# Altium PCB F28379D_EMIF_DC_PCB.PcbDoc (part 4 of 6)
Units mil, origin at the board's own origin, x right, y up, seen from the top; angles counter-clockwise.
Board outline 3000 x 1480 mil, 6 copper layers (Top Layer, Signal Layer 1, Signal Layer 2, Signal Layer 3, Signal Layer 4, Bottom Layer), stack 61.4 mil thick; 51 components, 68 nets, 414 pads, 205 vias.
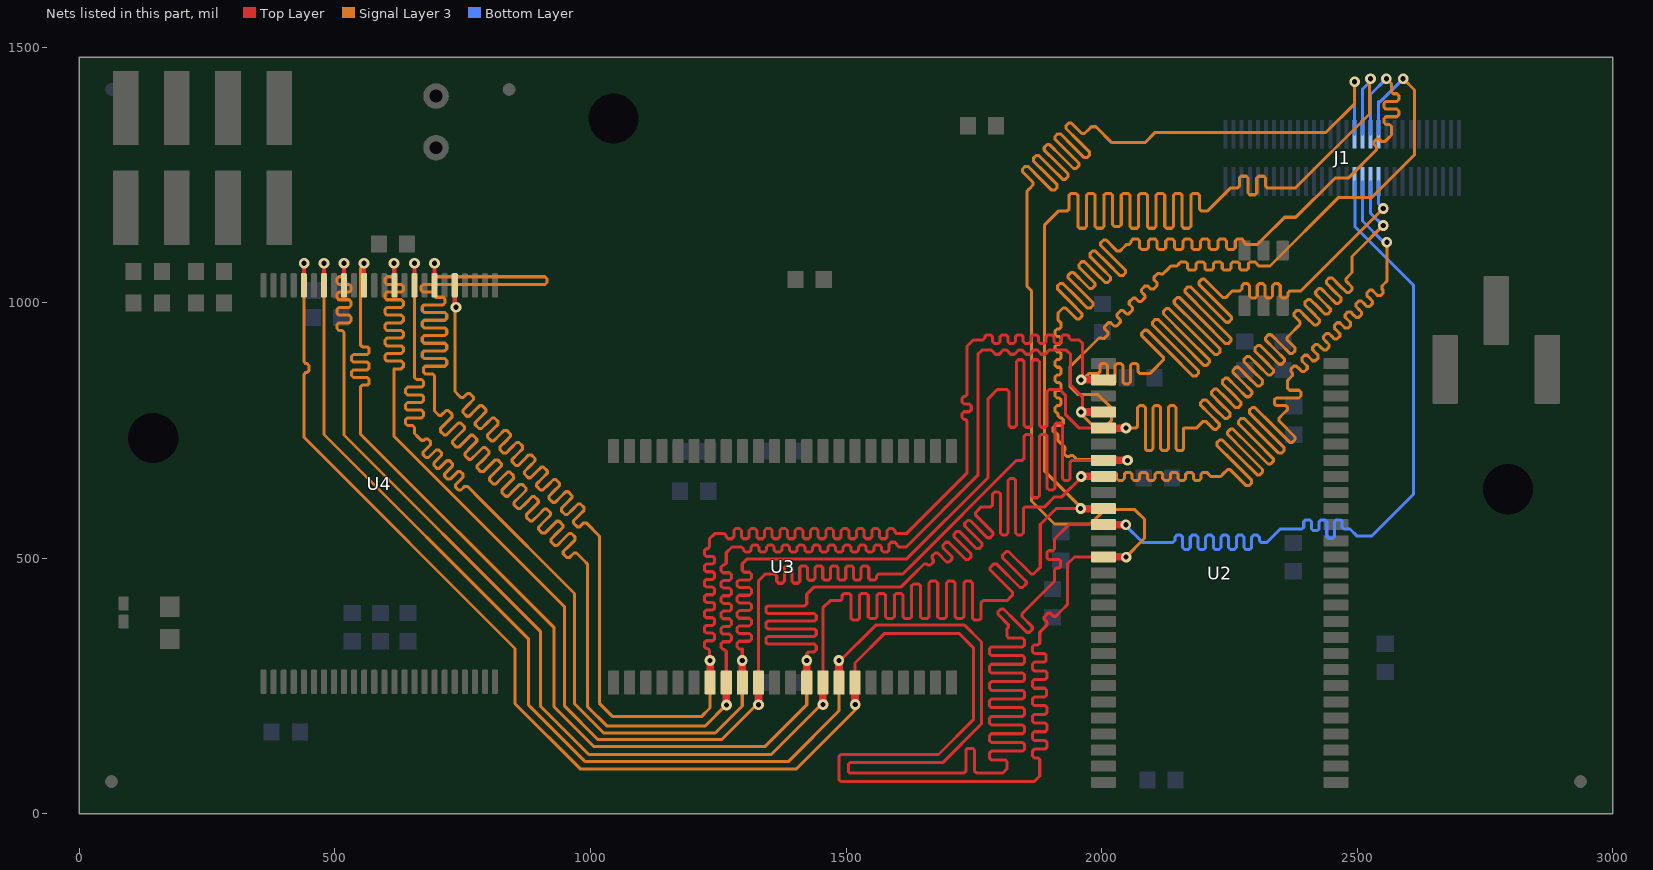
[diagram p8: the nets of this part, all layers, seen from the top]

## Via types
v1: diameter 21, hole 10, Top Layer to Bottom Layer, 204 vias
v2: diameter 20, hole 10, Top Layer to Bottom Layer, 1 vias

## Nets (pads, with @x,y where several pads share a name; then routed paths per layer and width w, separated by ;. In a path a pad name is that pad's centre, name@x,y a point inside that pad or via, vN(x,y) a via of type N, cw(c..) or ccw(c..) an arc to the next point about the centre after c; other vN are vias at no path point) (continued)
EM_D0: J1.21@2541.87,1236.74 U2.2 U3.7 U4.29 | length 6484.8
  Top Layer w6: v1@1234,297 1233,298 1233,316 1233,319.75 1229.25,323.5 1226.75,323.5 1223,327.25 1223,334.75 1226.75,338.5 1233,338.5 1239.25,338.5 1243,342.25 1243,349.75 1239.25,353.5 1233,353.5 1226.75,353.5 1223,357.25 1223,364.75 1226.75,368.5 1233,368.5 1239.25,368.5 1243,372.25 1243,379.75 1239.25,383.5 1233,383.5 1226.75,383.5 1223,387.25 1223,394.75 1226.75,398.5 1233,398.5 1239.25,398.5 1243,402.25 1243,409.75 1239.25,413.5 1233,413.5 1226.75,413.5 1223,417.25 1223,424.75 1226.75,428.5 1233,428.5 1239.25,428.5 1243,432.25 1243,439.75 1239.25,443.5 1233,443.5 1226.75,443.5 1223,447.25 1223,454.75 1226.75,458.5 1233,458.5 1239.25,458.5 1243,462.25 1243,469.75 1239.25,473.5 1233,473.5 1226.75,473.5 1223,477.25 1223,484.75 1226.75,488.5 1233,488.5 1239.25,488.5 1243,492.25 1243,499.75 1239.25,503.5 1233,503.5 1226.75,503.5 1223,507.25 1223,514.75 1226.75,518.5 1229.25,518.5 1233,522.25 1233,532 1233,538 1243,548 1250.5,548 1261.75,548 1265.5,544.25 1265.5,541.75 1269.25,538 1276.75,538 1280.5,541.75 1280.5,548 1280.5,554.25 1284.25,558 1291.75,558 1295.5,554.25 1295.5,548 1295.5,541.75 1299.25,538 1306.75,538 1310.5,541.75 1310.5,548 1310.5,554.25 1314.25,558 1321.75,558 1325.5,554.25 1325.5,548 1325.5,541.75 1329.25,538 1336.75,538 1340.5,541.75 1340.5,548 1340.5,554.25 1344.25,558 1351.75,558 1355.5,554.25 1355.5,548 1355.5,541.75 1359.25,538 1366.75,538 1370.5,541.75 1370.5,548 1370.5,554.25 1374.25,558 1381.75,558 1385.5,554.25 1385.5,548 1385.5,541.75 1389.25,538 1396.75,538 1400.5,541.75 1400.5,548 1400.5,554.25 1404.25,558 1411.75,558 1415.5,554.25 1415.5,548 1415.5,541.75 1419.25,538 1426.75,538 1430.5,541.75 1430.5,548 1430.5,554.25 1434.25,558 1441.75,558 1445.5,554.25 1445.5,548 1445.5,541.75 1449.25,538 1456.75,538 1460.5,541.75 1460.5,548 1460.5,554.25 1464.25,558 1471.75,558 1475.5,554.25 1475.5,548 1475.5,541.75 1479.25,538 1486.75,538 1490.5,541.75 1490.5,548 1490.5,554.25 1494.25,558 1501.75,558 1505.5,554.25 1505.5,548 1505.5,541.75 1509.25,538 1516.75,538 1520.5,541.75 1520.5,548 1520.5,554.25 1524.25,558 1531.75,558 1535.5,554.25 1535.5,548 1535.5,541.75 1539.25,538 1546.75,538 1550.5,541.75 1550.5,548 1550.5,554.25 1554.25,558 1561.75,558 1565.5,554.25 1565.5,548 1565.5,541.75 1569.25,538 1576.75,538 1580.5,541.75 1580.5,548 1580.5,554.25 1584.25,558 1591.75,558 1595.5,554.25 1595.5,551.75 1599.25,548 1610.5,548 1611,548 1618,548 1737,667 1737,764 1737,767.75 1733.25,771.5 1730.75,771.5 1727,775.25 1727,782.75 1730.75,786.5 1737,786.5 1741.25,786.5 1745,790.25 1745,797.75 1741.25,801.5 1737,801.5 1730.75,801.5 1727,805.25 1727,812.75 1730.75,816.5 1733.25,816.5 1737,820.25 1737,899 1737,915 1749,927 1764,927 1767.75,927 1771.5,930.75 1771.5,933.25 1775.25,937 1782.75,937 1786.5,933.25 1786.5,927 1786.5,923.75 1790.25,920 1797.75,920 1801.5,923.75 1801.5,927 1801.5,933.25 1805.25,937 1812.75,937 1816.5,933.25 1816.5,927 1816.5,923.75 1820.25,920 1827.75,920 1831.5,923.75 1831.5,927 1831.5,933.25 1835.25,937 1842.75,937 1846.5,933.25 1846.5,927 1846.5,923.75 1850.25,920 1857.75,920 1861.5,923.75 1861.5,927 1861.5,933.25 1865.25,937 1872.75,937 1876.5,933.25 1876.5,927 1876.5,923.75 1880.25,920 1887.75,920 1891.5,923.75 1891.5,927 1891.5,933.25 1895.25,937 1902.75,937 1906.5,933.25 1906.5,927 1906.5,923.75 1910.25,920 1917.75,920 1921.5,923.75 1921.5,927 1921.5,933.25 1925.25,937 1932.75,937 1936.5,933.25 1936.5,930.75 1940.25,927 1951.5,927 1956,927 1963.05,919.95 v1@1963.05,848.95
  Top Layer w8: U4.29@734.64,1033.8 734.64,996.36 v1@737,994
  Top Layer w15: U3.7@1234.27,256.62 v1@1234.27,290.73 ; v1@1963.05,848.95 U2.2@2003.64,848.95
  Signal Layer 3 w6: v1(737,991) v1@735,989 ; v1@737,994 735,992 v1@735,989 ; v1@1234,297 1234,207 1217,190 1044,190 1017.5,216.5 1017.5,540 1017.5,543.5 991.83,569.17 987.02,569.17 979.1,561.25 974.29,561.25 967.08,568.46 967.08,573.27 977.41,583.59 987.73,593.92 987.73,598.73 980.52,605.94 975.71,605.94 965.39,595.61 955.06,585.29 950.25,585.29 943.04,592.5 943.04,597.31 953.36,607.64 963.69,617.96 963.69,622.77 956.48,629.98 951.67,629.98 941.34,619.66 931.02,609.33 926.21,609.33 919,616.55 919,621.35 929.32,631.68 939.65,642 939.65,646.81 932.43,654.02 927.63,654.02 917.3,643.7 906.98,633.37 902.17,633.37 894.96,640.59 894.96,645.4 905.28,655.72 915.6,666.04 915.6,670.85 908.39,678.06 903.58,678.06 893.26,667.74 882.94,657.42 878.13,657.42 870.92,664.63 870.92,669.44 881.24,679.76 891.56,690.08 891.56,694.89 884.35,702.11 879.54,702.11 869.22,691.78 858.89,681.46 854.09,681.46 846.87,688.67 846.87,693.48 857.2,703.8 867.52,714.13 867.52,718.93 860.31,726.15 855.5,726.15 845.18,715.82 834.85,705.5 830.04,705.5 822.83,712.71 822.83,717.52 833.16,727.84 843.48,738.17 843.48,742.98 836.27,750.19 831.46,750.19 821.14,739.86 810.81,729.54 806,729.54 798.79,736.75 798.79,741.56 809.11,751.89 819.44,762.21 819.44,767.02 812.23,774.23 807.42,774.23 797.09,763.91 786.77,753.58 781.96,753.58 774.75,760.8 774.75,765.6 785.07,775.93 795.4,786.25 795.4,791.06 788.18,798.27 783.38,798.27 773.05,787.95 762.73,777.62 757.92,777.62 750.71,784.84 750.71,789.64 761.03,799.97 771.36,810.29 771.36,815.1 764.14,822.31 759.33,822.31 751.41,814.39 746.61,814.39 743,818 735,826 v1@735,989 ; v1@1963.05,848.95 1975.1,861 1982,861 1992.75,861 1996.5,864.75 1996.5,877.25 2000.25,881 2007.75,881 2011.5,877.25 2011.5,861 2011.5,844.75 2015.25,841 2022.75,841 2026.5,844.75 2026.5,861 2026.5,877.25 2030.25,881 2037.75,881 2041.5,877.25 2041.5,861 2041.5,844.75 2045.25,841 2052.75,841 2056.5,844.75 2056.5,861 2056.5,877.25 2060.25,881 2067.75,881 2071.5,877.25 2071.5,864.75 2075.25,861 2086.5,861 2094,861 2099,866 2120.77,887.77 2120.77,893.07 2078.52,935.32 2078.52,940.62 2083.82,945.93 2089.12,945.93 2134.02,901.02 2178.93,856.12 2184.23,856.12 2189.53,861.43 2189.53,866.73 2144.63,911.63 2099.73,956.53 2099.73,961.84 2105.03,967.14 2110.34,967.14 2155.24,922.24 2200.14,877.34 2205.44,877.34 2210.75,882.64 2210.75,887.94 2165.84,932.84 2120.94,977.75 2120.94,983.05 2126.25,988.35 2131.55,988.35 2176.45,943.45 2221.35,898.55 2226.66,898.55 2231.96,903.85 2231.96,909.16 2187.06,954.06 2142.16,998.96 2142.16,1004.26 2147.46,1009.57 2152.76,1009.57 2197.66,964.66 2242.57,919.76 2247.87,919.76 2253.17,925.07 2253.17,930.37 2208.27,975.27 2163.37,1020.17 2163.37,1025.48 2168.67,1030.78 2173.97,1030.78 2218.88,985.88 2243.22,961.53 2248.52,961.53 2253.83,966.84 2253.83,972.14 2229.48,996.48 2190.76,1035.21 2190.76,1040.51 2196.06,1045.82 2201.36,1045.82 2237.44,1009.74 2242.74,1009.74 2250.7,1017.7 2256,1023 2267,1023 2270.75,1023 2274.5,1026.75 2274.5,1033.25 2278.25,1037 2285.75,1037 2289.5,1033.25 2289.5,1023 2289.5,1012.75 2293.25,1009 2300.75,1009 2304.5,1012.75 2304.5,1023 2304.5,1033.25 2308.25,1037 2315.75,1037 2319.5,1033.25 2319.5,1023 2319.5,1012.75 2323.25,1009 2330.75,1009 2334.5,1012.75 2334.5,1023 2334.5,1033.25 2338.25,1037 2345.75,1037 2349.5,1033.25 2349.5,1023 2349.5,1012.75 2353.25,1009 2360.75,1009 2364.5,1012.75 2364.5,1019.25 2368.25,1023 2379.5,1023 2380,1023 2390,1023 v1(2551,1184)
  Bottom Layer w6: J1.21@2541.87,1236.74 2541.87,1193.13 v1(2551,1184)
  other v1: 1234,300 1960.05,848.95
EM_D1: J1.22@2541.87,1329.26 U2.4 U3.8 U4.31 | length 6431.8
  Top Layer w6: U3.8@1265.76,256.62 1265.76,314 1265.76,317.75 1262.01,321.5 1259.51,321.5 1255.76,325.25 1255.76,332.75 1259.51,336.5 1265.76,336.5 1272.01,336.5 1275.76,340.25 1275.76,347.75 1272.01,351.5 1265.76,351.5 1259.51,351.5 1255.76,355.25 1255.76,362.75 1259.51,366.5 1265.76,366.5 1272.01,366.5 1275.76,370.25 1275.76,377.75 1272.01,381.5 1265.76,381.5 1259.51,381.5 1255.76,385.25 1255.76,392.75 1259.51,396.5 1265.76,396.5 1272.01,396.5 1275.76,400.25 1275.76,407.75 1272.01,411.5 1265.76,411.5 1259.51,411.5 1255.76,415.25 1255.76,422.75 1259.51,426.5 1265.76,426.5 1272.01,426.5 1275.76,430.25 1275.76,437.75 1272.01,441.5 1265.76,441.5 1259.51,441.5 1255.76,445.25 1255.76,452.75 1259.51,456.5 1265.76,456.5 1272.01,456.5 1275.76,460.25 1275.76,467.75 1272.01,471.5 1265.76,471.5 1259.51,471.5 1255.76,475.25 1255.76,482.75 1259.51,486.5 1262.01,486.5 1265.76,490.25 1265.76,497 1265.76,510.76 1277,522 1284.5,522 1295.75,522 1299.5,518.25 1299.5,515.75 1303.25,512 1310.75,512 1314.5,515.75 1314.5,522 1317.89,525.39 1326.11,525.39 1329.5,522 1329.5,515.75 1333.25,512 1340.75,512 1344.5,515.75 1344.5,522 1347.89,525.39 1356.11,525.39 1359.5,522 1359.5,515.75 1363.25,512 1370.75,512 1374.5,515.75 1374.5,522 1377.89,525.39 1386.11,525.39 1389.5,522 1389.5,515.75 1393.25,512 1400.75,512 1404.5,515.75 1404.5,522 1407.89,525.39 1416.11,525.39 1419.5,522 1419.5,515.75 1423.25,512 1430.75,512 1434.5,515.75 1434.5,522 1437.89,525.39 1446.11,525.39 1449.5,522 1449.5,515.75 1453.25,512 1460.75,512 1464.5,515.75 1464.5,522 1467.89,525.39 1476.11,525.39 1479.5,522 1479.5,515.75 1483.25,512 1490.75,512 1494.5,515.75 1494.5,522 1497.89,525.39 1506.11,525.39 1509.5,522 1509.5,515.75 1513.25,512 1520.75,512 1524.5,515.75 1524.5,522 1527.89,525.39 1536.11,525.39 1539.5,522 1539.5,515.75 1543.25,512 1550.75,512 1554.5,515.75 1554.5,522 1557.89,525.39 1566.11,525.39 1569.5,522 1569.5,515.75 1573.25,512 1580.75,512 1584.5,515.75 1584.5,522 1584.5,527.37 1588.25,531.12 1595.75,531.12 1599.5,527.37 1599.5,525.75 1603.25,522 1605,522 1618,522 1758,662 1758,899 1766,907 1773.5,907 1784.75,907 1788.5,903.25 1788.5,902.75 1792.25,899 1799.75,899 1803.5,902.75 1803.5,903.25 1807.25,907 1814.75,907 1818.5,903.25 1818.5,902.75 1822.25,899 1829.75,899 1833.5,902.75 1833.5,903.25 1837.25,907 1844.75,907 1848.5,903.25 1848.5,902.75 1852.25,899 1859.75,899 1863.5,902.75 1863.5,903.25 1867.25,907 1874.75,907 1878.5,903.25 1878.5,902.75 1882.25,899 1889.75,899 1893.5,902.75 1893.5,903.25 1897.25,907 1908.5,907 1923.5,907 1926,907 1931,907 1939,899 1939,839 1963.04,814.96 v1@1963.04,785.96
  Top Layer w8: v1@695,1076 695.27,1075.73 U4.31@695.27,1033.8
  Top Layer w15: U3.8@1265.76,256.62 1265.76,222.24 v1@1266,222 ; v1@1963.04,785.96 U2.4@2003.64,785.96
  Signal Layer 3 w6: v1@695,1073 695,1065.5 695,1054.25 698.75,1050.5 911.25,1050.5 915,1046.75 915,1039.25 911.25,1035.5 695,1035.5 672.75,1035.5 669,1031.75 669,1024.25 672.75,1020.5 691.25,1020.5 695,1016.75 695,1013 697.5,1010.5 711.95,1010.5 715.7,1006.75 715.7,999.25 711.95,995.5 695,995.5 674.75,995.5 671,991.75 671,984.25 674.75,980.5 695,980.5 715.25,980.5 719,976.75 719,969.25 715.25,965.5 695,965.5 674.75,965.5 671,961.75 671,954.25 674.75,950.5 695,950.5 715.25,950.5 719,946.75 719,939.25 715.25,935.5 695,935.5 674.75,935.5 671,931.75 671,924.25 674.75,920.5 695,920.5 715.25,920.5 719,916.75 719,909.25 715.25,905.5 695,905.5 674.75,905.5 671,901.75 671,894.25 674.75,890.5 695,890.5 715.25,890.5 719,886.75 719,879.25 715.25,875.5 695,875.5 676.82,875.5 673.07,871.75 673.07,864.25 676.82,860.5 691.25,860.5 695,856.75 695,853 695,788 700,783 703.61,779.39 708.41,779.39 717.61,788.59 722.41,788.59 729.63,781.37 729.63,776.56 718.03,764.97 706.44,753.37 706.44,748.56 713.65,741.35 718.46,741.35 730.05,752.95 741.65,764.54 746.46,764.54 753.67,757.33 753.67,752.52 742.07,740.93 730.48,729.33 730.48,724.52 737.69,717.31 742.5,717.31 754.09,728.91 765.69,740.5 770.5,740.5 777.71,733.29 777.71,728.48 766.11,716.89 754.52,705.29 754.52,700.48 761.73,693.27 766.54,693.27 778.14,704.86 789.73,716.46 794.54,716.46 801.75,709.25 801.75,704.44 790.16,692.84 778.56,681.25 778.56,676.44 785.77,669.23 790.58,669.23 802.18,680.82 813.77,692.42 818.58,692.42 825.79,685.21 825.79,680.4 814.2,668.8 802.6,657.21 802.6,652.4 809.81,645.19 814.62,645.19 826.22,656.78 837.81,668.38 842.62,668.38 849.84,661.16 849.84,656.36 838.24,644.76 826.64,633.16 826.64,628.36 833.86,621.14 838.66,621.14 850.26,632.74 861.86,644.34 866.66,644.34 873.88,637.12 873.88,632.31 862.28,620.72 850.69,609.12 850.69,604.31 857.9,597.1 862.71,597.1 874.3,608.7 885.9,620.29 890.71,620.29 897.92,613.08 897.92,608.27 886.32,596.68 874.73,585.08 874.73,580.27 881.94,573.06 886.75,573.06 898.34,584.66 909.94,596.25 914.75,596.25 921.96,589.04 921.96,584.23 910.36,572.64 898.77,561.04 898.77,556.23 905.98,549.02 910.79,549.02 922.39,560.61 933.98,572.21 938.79,572.21 946,565 946,560.19 934.41,548.59 922.81,537 922.81,532.19 930.02,524.98 934.83,524.98 946.43,536.57 958.02,548.17 962.83,548.17 970.04,540.96 970.04,536.15 958.45,524.55 946.85,512.96 946.85,508.15 954.06,500.94 958.87,500.94 968.06,510.13 972.87,510.13 987.5,495.5 994,489 994,210 1032,172 1225,172 v1(1266,213) ; v1@1264,215 v1@1266,217 ; v1@1963.04,785.96 1963.04,778.96 1986,756 2006,756 2019,769 2019,794 1993,820 1954,820 1938,836 1938,874 1994.86,930.86 1999.66,930.86 2000.51,930.01 2005.32,930.01 2012.53,937.22 2012.53,942.03 2009.28,945.28 2006.03,948.53 2006.03,953.34 2013.24,960.55 2018.05,960.55 2021.3,957.3 2024.55,954.05 2029.36,954.05 2036.58,961.26 2036.58,966.07 2033.32,969.32 2030.07,972.58 2030.07,977.38 2037.28,984.6 2042.09,984.6 2045.34,981.34 2048.6,978.09 2053.4,978.09 2060.62,985.3 2060.62,990.11 2057.36,993.36 2054.11,996.62 2054.11,1001.43 2061.32,1008.64 2066.13,1008.64 2069.39,1005.39 2072.64,1002.13 2077.45,1002.13 2084.66,1009.35 2084.66,1014.15 2081.41,1017.41 2078.15,1020.66 2078.15,1025.47 2085.37,1032.68 2090.17,1032.68 2093.43,1029.43 2096.68,1026.17 2101.49,1026.17 2108.7,1033.39 2108.7,1038.2 2105.45,1041.45 2102.2,1044.7 2102.2,1049.51 2109.41,1056.72 2114.22,1056.72 2115.06,1055.87 2119.87,1055.87 2129.49,1065.49 2135.5,1071.5 2147.6,1071.5 2151,1074.9 2151,1076.1 2154.4,1079.5 2164.6,1079.5 2168,1076.1 2168,1071.5 2168,1066.9 2171.4,1063.5 2181.6,1063.5 2185,1066.9 2185,1071.5 2185,1076.1 2188.4,1079.5 2198.6,1079.5 2202,1076.1 2202,1071.5 2202,1066.9 2205.4,1063.5 2215.6,1063.5 2219,1066.9 2219,1071.5 2219,1076.1 2222.4,1079.5 2232.6,1079.5 2236,1076.1 2236,1071.5 2236,1066.9 2239.4,1063.5 2249.6,1063.5 2253,1066.9 2253,1071.5 2253,1076.1 2256.4,1079.5 2266.6,1079.5 2270,1076.1 2270,1071.5 2270,1066.9 2273.4,1063.5 2283.6,1063.5 2287,1066.9 2287,1071.5 2287,1076.1 2290.4,1079.5 2300.6,1079.5 2304,1076.1 2304,1074.9 2307.4,1071.5 2321,1071.5 2329.5,1071.5 2464,1206 2529,1206 2612,1289 2612,1416 v1(2590,1438) ; v1@2587,1438 v1@2588.5,1436.5
  Bottom Layer w6: J1.22@2541.87,1329.26 2541.87,1392.87 2544.87,1392.87 v1(2590,1438)
  other v1: 1960.04,785.96 695,1077
EM_D2: J1.23@2526.12,1236.74 U2.5 U3.9 U4.33 | length 6444.2
  Top Layer w6: v1@1297,297 v1(1297,300) 1297,322 1296.5,322.5 1290.77,322.5 1287.02,326.25 1287.02,333.75 1290.77,337.5 1297,337.5 1311.25,337.5 1315,341.25 1315,348.75 1311.25,352.5 1297,352.5 1290.77,352.5 1287.02,356.25 1287.02,363.75 1290.77,367.5 1297,367.5 1311.25,367.5 1315,371.25 1315,378.75 1311.25,382.5 1297,382.5 1290.77,382.5 1287.02,386.25 1287.02,393.75 1290.77,397.5 1297,397.5 1311.25,397.5 1315,401.25 1315,408.75 1311.25,412.5 1297,412.5 1290.77,412.5 1287.02,416.25 1287.02,423.75 1290.77,427.5 1297,427.5 1311.25,427.5 1315,431.25 1315,438.75 1311.25,442.5 1297,442.5 1290.77,442.5 1287.02,446.25 1287.02,453.75 1290.77,457.5 1297,457.5 1311.25,457.5 1315,461.25 1315,468.75 1311.25,472.5 1300.75,472.5 1297,476.25 1297,480 1297,489 1306,498 1618,498 1778,658 1778,812 1796,830 1803.5,830 1814.75,830 1818.5,826.25 1818.5,759.88 1822.25,756.13 1829.75,756.13 1833.5,759.88 1833.5,830 1833.5,884.5 1837.25,888.25 1844.75,888.25 1848.5,884.5 1848.5,830 1848.5,759.88 1852.25,756.13 1859.75,756.13 1863.5,759.88 1863.5,830 1863.5,884.5 1867.25,888.25 1874.75,888.25 1878.5,884.5 1878.5,830 1878.5,759.88 1882.25,756.13 1889.75,756.13 1893.5,759.88 1893.5,826.25 1897.25,830 1918,830 1929,819 1929,781.46 1956,754.46 U2.5@2003.64,754.46
  Top Layer w8: U4.33@655.9,1033.8 655.9,1075.9 v1@656,1076
  Top Layer w15: U3.9@1297.26,256.62 v1@1297.26,290.74 ; U2.5@2003.64,754.46 v1(2047.54,754.46)
  Signal Layer 3 w6: v1@656,1073 656,857 656,853.25 659.75,849.5 669.89,849.5 673.64,845.75 673.64,838.25 669.89,834.5 656,834.5 642.11,834.5 638.36,830.75 638.36,823.25 642.11,819.5 656,819.5 669.89,819.5 673.64,815.75 673.64,808.25 669.89,804.5 656,804.5 642.11,804.5 638.36,800.75 638.36,793.25 642.11,789.5 656,789.5 669.89,789.5 673.64,785.75 673.64,778.25 669.89,774.5 656,774.5 642.11,774.5 638.36,770.75 638.36,763.25 642.11,759.5 652.25,759.5 656,755.75 656,744.5 656,744 661.3,738.7 669.26,730.74 674.56,730.74 676.81,732.99 682.12,732.99 687.42,727.69 687.42,722.39 682.52,717.48 672.69,707.66 672.69,702.36 678,697.05 683.3,697.05 693.12,706.88 698.03,711.78 703.33,711.78 708.63,706.48 708.63,701.18 703.73,696.27 693.91,686.45 693.91,681.14 699.21,675.84 704.51,675.84 714.34,685.66 719.24,690.57 724.54,690.57 729.85,685.27 729.85,679.96 724.94,675.06 715.12,665.23 715.12,659.93 720.42,654.63 725.73,654.63 735.55,664.45 740.45,669.36 745.76,669.36 751.06,664.05 751.06,658.75 746.16,653.84 736.33,644.02 736.33,638.72 741.63,633.41 746.94,633.41 754.11,640.59 759.41,640.59 787.5,612.5 969,431 969,215 1026,158 1244,158 1297,211 v1@1297,297 ; v1(2047.54,754.46) 2063,754.46 2066.75,754.46 2070.5,758.21 2070.5,794.71 2074.25,798.46 2081.75,798.46 2085.5,794.71 2085.5,754.46 2085.5,714.21 2089.25,710.46 2096.75,710.46 2100.5,714.21 2100.5,754.46 2100.5,794.71 2104.25,798.46 2111.75,798.46 2115.5,794.71 2115.5,754.46 2115.5,714.21 2119.25,710.46 2126.75,710.46 2130.5,714.21 2130.5,754.46 2130.5,794.71 2134.25,798.46 2141.75,798.46 2145.5,794.71 2145.5,754.46 2145.5,714.21 2149.25,710.46 2156.75,710.46 2160.5,714.21 2160.5,753.96 2161,754.46 2185.46,754.46 2190.77,759.77 2198.72,767.72 2204.03,767.72 2219.61,752.14 2224.91,752.14 2230.22,757.44 2230.22,762.74 2211.98,780.98 2193.74,799.22 2193.74,804.52 2199.05,809.82 2204.35,809.82 2222.59,791.59 2240.82,773.35 2246.13,773.35 2251.43,778.65 2251.43,783.96 2233.19,802.19 2214.96,820.43 2214.96,825.73 2220.26,831.04 2225.56,831.04 2243.8,812.8 2262.04,794.56 2267.34,794.56 2272.64,799.87 2272.64,805.17 2254.41,823.41 2236.17,841.64 2236.17,846.95 2241.47,852.25 2246.78,852.25 2265.01,834.01 2283.25,815.78 2288.55,815.78 2293.86,821.08 2293.86,826.38 2275.62,844.62 2257.38,862.86 2257.38,868.16 2262.69,873.46 2267.99,873.46 2286.23,855.23 2304.46,836.99 2309.77,836.99 2315.07,842.29 2315.07,847.6 2296.83,865.83 2278.6,884.07 2278.6,889.37 2283.9,894.68 2289.2,894.68 2307.44,876.44 2325.68,858.2 2330.98,858.2 2336.28,863.51 2336.28,868.81 2318.05,887.05 2299.81,905.28 2299.81,910.59 2305.11,915.89 2310.42,915.89 2328.65,897.65 2346.89,879.42 2352.19,879.42 2357.5,884.72 2357.5,890.02 2339.26,908.26 2321.02,926.5 2321.02,931.8 2326.33,937.1 2331.63,937.1 2349.87,918.87 2368.1,900.63 2373.41,900.63 2378.71,905.93 2378.71,911.24 2363.12,926.82 2363.12,932.12 2367.5,936.5 2385.5,954.5 2388.15,957.15 2388.15,962.45 2376.48,974.12 2376.48,979.43 2381.79,984.73 2387.09,984.73 2401.41,970.41 2415.73,956.09 2421.03,956.09 2426.34,961.39 2426.34,966.7 2412.02,981.02 2397.7,995.34 2397.7,1000.64 2403,1005.94 2408.3,1005.94 2422.62,991.62 2436.94,977.3 2442.25,977.3 2447.55,982.61 2447.55,987.91 2433.23,1002.23 2418.91,1016.55 2418.91,1021.85 2424.21,1027.16 2429.52,1027.16 2443.84,1012.84 2458.16,998.52 2463.46,998.52 2468.76,1003.82 2468.76,1009.12 2454.44,1023.44 2440.12,1037.76 2440.12,1043.07 2445.43,1048.37 2450.73,1048.37 2465.05,1034.05 2479.37,1019.73 2484.67,1019.73 2489.97,1025.03 2489.97,1030.34 2478.31,1042 2478.31,1047.31 2485,1054 2490,1059 2490,1090 v1(2551,1151)
  Bottom Layer w6: J1.23@2526.12,1236.74 2526.12,1174.88 2550,1151 v1(2551,1151)
  other v1: 656,1077
EM_D3: J1.24@2526.12,1329.26 U2.7 U3.10 U4.35 | length 6434
  Top Layer w6: U3.10@1328.76,256.62 1328.76,455.76 1342,469 1349.5,469 1360.75,469 1364.5,465.25 1364.5,454.75 1368.25,451 1375.75,451 1379.5,454.75 1379.5,469 1379.5,481.25 1383.25,485 1390.75,485 1394.5,481.25 1394.5,469 1394.5,454.75 1398.25,451 1405.75,451 1409.5,454.75 1409.5,469 1409.5,481.25 1413.25,485 1420.75,485 1424.5,481.25 1424.5,469 1424.5,460.55 1428.25,456.8 1435.75,456.8 1439.5,460.55 1439.5,469 1439.5,481.25 1443.25,485 1450.75,485 1454.5,481.25 1454.5,469 1454.5,460.75 1458.25,457 1465.75,457 1469.5,460.75 1469.5,469 1469.5,481.25 1473.25,485 1480.75,485 1484.5,481.25 1484.5,469 1484.5,460.75 1488.25,457 1495.75,457 1499.5,460.75 1499.5,469 1499.5,481.25 1503.25,485 1510.75,485 1514.5,481.25 1514.5,469 1514.5,460.75 1518.25,457 1525.75,457 1529.5,460.75 1529.5,469 1529.5,481.25 1533.25,485 1540.75,485 1544.5,481.25 1544.5,469 1544.5,460.75 1548.25,457 1555.75,457 1559.5,460.75 1559.5,465.25 1563.25,469 1611,469 1616.3,474.3 1626.5,484.5 1833.47,691.47 1841,691.47 1844.75,691.47 1848.5,695.22 1848.5,738.62 1852.25,742.37 1859.75,742.37 1863.5,738.62 1863.5,691.47 1863.5,621.98 1867.25,618.23 1874.75,618.23 1878.5,621.98 1878.5,691.47 1878.5,738.62 1882.25,742.37 1889.75,742.37 1893.5,738.62 1893.5,691.47 1893.5,637.1 1897.25,633.35 1904.75,633.35 1908.5,637.1 1908.5,691.47 1908.5,760.96 1912.25,764.71 1919.75,764.71 1923.5,760.96 1923.5,691.47 1923.5,655.6 1927.25,651.85 1934.75,651.85 1938.5,655.6 1938.5,687.72 1942.25,691.47 1947,691.47 U2.7@2003.64,691.47
  Top Layer w8: v1@616,1076 616.53,1075.47 U4.35@616.53,1033.8
  Top Layer w15: v1@1328.76,222.24 U3.10@1328.76,256.62 ; U2.7@2003.64,691.47 v1(2050.53,691.47)
  Signal Layer 3 w6: v1@616,1073 616,1065.5 616,1054.25 612.25,1050.5 601.79,1050.5 598.04,1046.75 598.04,1039.25 601.79,1035.5 616,1035.5 630.21,1035.5 633.96,1031.75 633.96,1024.25 630.21,1020.5 616,1020.5 601.79,1020.5 598.04,1016.75 598.04,1009.25 601.79,1005.5 616,1005.5 630.21,1005.5 633.96,1001.75 633.96,994.25 630.21,990.5 616,990.5 601.79,990.5 598.04,986.75 598.04,979.25 601.79,975.5 616,975.5 630.21,975.5 633.96,971.75 633.96,964.25 630.21,960.5 616,960.5 601.79,960.5 598.04,956.75 598.04,949.25 601.79,945.5 616,945.5 630.21,945.5 633.96,941.75 633.96,934.25 630.21,930.5 616,930.5 601.79,930.5 598.04,926.75 598.04,919.25 601.79,915.5 616,915.5 630.21,915.5 633.96,911.75 633.96,904.25 630.21,900.5 616,900.5 601.79,900.5 598.04,896.75 598.04,889.25 601.79,885.5 616,885.5 630.21,885.5 633.96,881.75 633.96,874.25 630.21,870.5 616.5,870.5 616,870 616,738 949.5,404.5 949.5,210.5 1015,145 1256.51,145 v1@1328.76,217.24 ; v1(2050.53,691.47) 2049,693 2038,693 2030.75,693 2028.5,695.25 2024.75,699 2017.25,699 2013.5,695.25 2013.5,693 2013.5,690.75 2009.75,687 2002.25,687 1998.5,690.75 1998.5,693 1998.5,695.25 1994.75,699 1987.25,699 1983.5,695.25 1981.25,693 1976,693 1952,693 1948.5,696.5 1944.17,700.83 1938.86,700.83 1937.1,699.06 1931.79,699.06 1926.49,704.37 1926.49,709.67 1928.26,711.44 1928.26,716.74 1920.3,724.7 1915,730 1915,740.75 1911.25,744.5 1908.75,744.5 1905,748.25 1905,755.75 1908.75,759.5 1915,759.5 1921.25,759.5 1925,763.25 1925,770.75 1921.25,774.5 1918.75,774.5 1915,778.25 1915,782 1913.5,783.5 1912.75,783.5 1909,787.25 1909,794.75 1912.75,798.5 1915,798.5 1917.25,798.5 1921,802.25 1921,809.75 1917.25,813.5 1915,813.5 1912.75,813.5 1909,817.25 1909,824.75 1912.75,828.5 1915,828.5 1917.25,828.5 1921,832.25 1921,839.75 1917.25,843.5 1915,843.5 1912.75,843.5 1909,847.25 1909,854.75 1912.75,858.5 1915,858.5 1917.25,858.5 1921,862.25 1921,869.75 1917.25,873.5 1915,873.5 1912.75,873.5 1909,877.25 1909,884.75 1912.75,888.5 1915,888.5 1917.25,888.5 1921,892.25 1921,899.75 1917.25,903.5 1915,903.5 1912.75,903.5 1909,907.25 1909,914.75 1912.75,918.5 1915,918.5 1917.25,918.5 1921,922.25 1921,929.75 1917.25,933.5 1915,933.5 1912.75,933.5 1909,937.25 1909,944.75 1912.75,948.5 1915,948.5 1917.25,948.5 1921,952.25 1921,959.75 1917.25,963.5 1915,965.75 1915,971 1915,980 1917.5,982.5 1924.37,989.37 1929.68,989.37 1951.24,967.81 1956.55,967.81 1961.85,973.11 1961.85,978.41 1937.63,1002.63 1913.41,1026.85 1913.41,1032.15 1918.72,1037.46 1924.02,1037.46 1948.24,1013.24 1972.46,989.02 1977.76,989.02 1983.06,994.32 1983.06,999.63 1958.84,1023.84 1934.63,1048.06 1934.63,1053.37 1939.93,1058.67 1945.23,1058.67 1969.45,1034.45 1976.2,1027.7 1981.5,1027.7 1986.81,1033 1986.81,1038.31 1980.06,1045.06 1955.84,1069.28 1955.84,1074.58 1961.14,1079.88 1966.45,1079.88 1990.66,1055.66 2006.95,1039.38 2012.26,1039.38 2017.56,1044.68 2017.56,1049.98 2001.27,1066.27 1977.05,1090.49 1977.05,1095.79 1982.36,1101.1 1987.66,1101.1 2011.88,1076.88 2036.1,1052.66 2041.4,1052.66 2046.7,1057.96 2046.7,1063.27 2022.48,1087.48 1998.27,1111.7 1998.27,1117.01 2003.57,1122.31 2008.87,1122.31 2030.44,1100.74 2035.74,1100.74 2043.7,1108.7 2049,1114 2054.1,1114 2057.5,1117.4 2057.5,1120.6 2060.9,1124 2071.1,1124 2074.5,1120.6 2074.5,1114 2074.5,1107.4 2077.9,1104 2088.1,1104 2091.5,1107.4 2091.5,1114 2091.5,1120.6 2094.9,1124 2105.1,1124 2108.5,1120.6 2108.5,1114 2108.5,1107.4 2111.9,1104 2122.1,1104 2125.5,1107.4 2125.5,1114 2125.5,1120.6 2128.9,1124 2139.1,1124 2142.5,1120.6 2142.5,1114 2142.5,1107.4 2145.9,1104 2156.1,1104 2159.5,1107.4 2159.5,1114 2159.5,1120.6 2162.9,1124 2173.1,1124 2176.5,1120.6 2176.5,1114 2176.5,1107.4 2179.9,1104 2190.1,1104 2193.5,1107.4 2193.5,1114 2193.5,1120.6 2196.9,1124 2207.1,1124 2210.5,1120.6 2210.5,1114 2210.5,1107.4 2213.9,1104 2224.1,1104 2227.5,1107.4 2227.5,1114 2227.5,1120.6 2230.9,1124 2241.1,1124 2244.5,1120.6 2244.5,1114 2244.5,1107.4 2247.9,1104 2258.1,1104 2261.5,1107.4 2261.5,1114 2261.5,1120.6 2264.9,1124 2275.1,1124 2278.5,1120.6 2278.5,1117.4 2281.9,1114 2305,1114 2311.01,1120.01 2317.5,1126.5 2358,1167 2380,1167 2456.5,1243.5 2482.5,1243.5 2537.83,1298.83 2537.83,1304.14 2532.83,1309.13 2532.83,1314.44 2538.14,1319.74 2543.44,1319.74 2548.44,1314.74 2553.74,1314.74 2561.7,1322.7 2567,1328 2567,1344.75 2563.25,1348.5 2556.18,1348.5 2552.43,1352.25 2552.43,1359.75 2556.18,1363.5 2567,1363.5 2577.82,1363.5 2581.57,1367.25 2581.57,1374.75 2577.82,1378.5 2567,1378.5 2556.18,1378.5 2552.43,1382.25 2552.43,1389.75 2556.18,1393.5 2567,1393.5 2577.82,1393.5 2581.57,1397.25 2581.57,1404.75 2577.82,1408.5 2570.75,1408.5 2567,1412.25 2567,1416 2567,1428 v1(2557,1438) ; v1@2554,1438 v1@2555.5,1436.5
  Bottom Layer w6: J1.24@2526.12,1329.26 2526.12,1407.12 v1(2557,1438)
  other v1: 1328.76,213.24 616,1077
EM_D4: J1.25@2510.37,1236.74 U2.8 U3.13 U4.38 | length 6442.5
  Top Layer w6: v1@1423.24,296.76 v1(1423.24,299.76) 1423.24,305 1423.24,312.99 1426.99,316.74 1437.99,316.74 1441.74,320.49 1441.74,327.99 1437.99,331.74 1423.24,331.74 1346.99,331.74 1343.24,335.49 1343.24,342.99 1346.99,346.74 1423.24,346.74 1437.99,346.74 1441.74,350.49 1441.74,357.99 1437.99,361.74 1423.24,361.74 1346.99,361.74 1343.24,365.49 1343.24,372.99 1346.99,376.74 1423.24,376.74 1437.99,376.74 1441.74,380.49 1441.74,387.99 1437.99,391.74 1423.24,391.74 1346.99,391.74 1343.24,395.49 1343.24,402.99 1346.99,406.74 1419.49,406.74 1423.24,410.49 1423.24,421.74 1423.24,429.24 1438,444 1608,444 1639.5,475.5 1644.8,480.8 1652.76,488.76 1658.06,488.76 1660.08,486.74 1665.38,486.74 1670.68,492.05 1670.68,497.35 1668.67,499.36 1668.67,504.67 1673.97,509.97 1679.27,509.97 1696.55,492.7 1701.85,492.7 1707.15,498 1707.15,503.31 1689.88,520.58 1689.88,525.88 1695.18,531.18 1700.49,531.18 1734.17,497.5 1739.47,497.5 1744.78,502.81 1744.78,508.11 1711.09,541.79 1711.09,547.09 1716.4,552.4 1721.7,552.4 1755.38,518.72 1760.69,518.72 1765.99,524.02 1765.99,529.32 1732.31,563 1732.31,568.31 1737.61,573.61 1742.91,573.61 1776.6,539.93 1781.9,539.93 1787.2,545.23 1787.2,550.54 1753.52,584.22 1753.52,589.52 1761.48,597.48 1764.5,600.5 1772,600.5 1783.25,600.5 1787,604.25 1787,625.75 1790.75,629.5 1798.25,629.5 1802,625.75 1802,600.5 1802,549.12 1805.75,545.37 1813.25,545.37 1817,549.12 1817,600.5 1817,651.88 1820.75,655.63 1828.25,655.63 1832,651.88 1832,600.5 1832,549.12 1835.75,545.37 1843.25,545.37 1847,549.12 1847,596.75 1850.75,600.5 1882,600.5 1888.5,600.5 1908,620 1922.05,620 v1@1962.02,659.98
  Top Layer w8: v1@557,1076 557.47,1075.53 U4.38@557.47,1033.8
  Top Layer w15: U3.13@1423.24,256.62 v1@1423.24,291.76 ; v1@1962.02,659.98 U2.8@2003.64,659.98
  Signal Layer 3 w6: v1@557,1073 550,1066 550,921 550,917.25 553.75,913.5 563.5,913.5 567.25,909.75 567.25,902.25 563.5,898.5 550,898.5 536.5,898.5 532.75,894.75 532.75,887.25 536.5,883.5 550,883.5 563.5,883.5 567.25,879.75 567.25,872.25 563.5,868.5 550,868.5 536.5,868.5 532.75,864.75 532.75,857.25 536.5,853.5 550,853.5 563.5,853.5 567.25,849.75 567.25,842.25 563.5,838.5 553.75,838.5 550,834.75 550,770 550,743 929,364 929,209 1006,132 1342.24,132 1423.24,213 v1@1423.24,296.76 ; v1@1962.02,659.98 1977,659.98 1980.75,659.98 1984.5,663.73 1984.5,664.23 1988.25,667.98 1995.75,667.98 1999.5,664.23 1999.5,659.98 1999.5,655.73 2003.25,651.98 2010.75,651.98 2014.5,655.73 2014.5,659.98 2014.5,664.23 2018.25,667.98 2025.75,667.98 2029.5,664.23 2029.5,659.98 2029.5,655.73 2033.25,651.98 2040.75,651.98 2044.5,655.73 2044.5,659.98 2044.5,664.23 2048.25,667.98 2055.75,667.98 2059.5,664.23 2059.5,659.98 2059.5,655.73 2063.25,651.98 2070.75,651.98 2074.5,655.73 2074.5,659.98 2074.5,664.23 2078.25,667.98 2085.75,667.98 2089.5,664.23 2089.5,659.98 2089.5,655.73 2093.25,651.98 2100.75,651.98 2104.5,655.73 2104.5,659.98 2104.5,664.23 2108.25,667.98 2115.75,667.98 2119.5,664.23 2119.5,659.98 2119.5,655.73 2123.25,651.98 2130.75,651.98 2134.5,655.73 2134.5,659.98 2134.5,664.23 2138.25,667.98 2145.75,667.98 2149.5,664.23 2149.5,659.98 2149.5,655.73 2153.25,651.98 2160.75,651.98 2164.5,655.73 2164.5,659.98 2164.5,664.23 2168.25,667.98 2175.75,667.98 2179.5,664.23 2179.5,659.98 2179.5,655.73 2183.25,651.98 2190.75,651.98 2194.5,655.73 2194.5,659.98 2194.5,664.23 2198.25,667.98 2205.75,667.98 2209.5,664.23 2209.5,663.73 2213.25,659.98 2223,659.98 2232.98,659.98 2238.28,665.28 2246.23,673.23 2251.54,673.23 2283,641.77 2288.31,641.77 2293.61,647.07 2293.61,652.37 2259.49,686.49 2225.37,720.61 2225.37,725.91 2230.68,731.22 2235.98,731.22 2270.1,697.1 2304.22,662.98 2309.52,662.98 2314.82,668.28 2314.82,673.59 2280.71,707.71 2246.59,741.82 2246.59,747.13 2251.89,752.43 2257.19,752.43 2291.31,718.31 2325.43,684.19 2330.73,684.19 2336.04,689.5 2336.04,694.8 2301.92,728.92 2267.8,763.04 2267.8,768.34 2273.1,773.64 2278.41,773.64 2312.53,739.53 2346.64,705.41 2351.95,705.41 2357.25,710.71 2357.25,716.01 2323.13,750.13 2289.01,784.25 2289.01,789.55 2294.32,794.86 2299.62,794.86 2333.74,760.74 2367.86,726.62 2373.16,726.62 2378.46,731.92 2378.46,737.23 2347,768.69 2347,774 2354.95,781.95 2364,791 2364,794.75 2360.25,798.5 2341.75,798.5 2338,802.25 2338,809.75 2341.75,813.5 2364,813.5 2386.25,813.5 2390,817.25 2390,824.75 2386.25,828.5 2367.75,828.5 2364,832.25 2364,843.5 2364,844 2364,848 2370.5,854.5 2373.15,857.15 2373.15,862.45 2370.48,865.13 2370.48,870.43 2375.78,875.74 2381.08,875.74 2386.41,870.41 2391.74,865.08 2397.04,865.08 2402.34,870.39 2402.34,875.69 2397.02,881.02 2391.69,886.34 2391.69,891.65 2396.99,896.95 2402.3,896.95 2407.62,891.62 2412.95,886.3 2418.25,886.3 2423.56,891.6 2423.56,896.9 2418.23,902.23 2412.9,907.56 2412.9,912.86 2418.21,918.16 2423.51,918.16 2428.84,912.84 2434.16,907.51 2439.47,907.51 2444.77,912.81 2444.77,918.12 2439.44,923.44 2434.12,928.77 2434.12,934.07 2439.42,939.38 2444.72,939.38 2450.05,934.05 2455.38,928.72 2460.68,928.72 2465.98,934.03 2465.98,939.33 2460.66,944.66 2455.33,949.98 2455.33,955.29 2460.63,960.59 2465.94,960.59 2471.26,955.26 2476.59,949.94 2481.89,949.94 2487.2,955.24 2487.2,960.54 2481.87,965.87 2476.54,971.2 2476.54,976.5 2481.85,981.8 2487.15,981.8 2492.48,976.48 2497.8,971.15 2503.11,971.15 2508.41,976.45 2508.41,981.76 2503.08,987.08 2497.76,992.41 2497.76,997.71 2503.06,1003.02 2508.36,1003.02 2513.69,997.69 2519.02,992.36 2524.32,992.36 2529.62,997.67 2529.62,1002.97 2524.3,1008.3 2518.97,1013.62 2518.97,1018.93 2524.27,1024.23 2529.58,1024.23 2534.9,1018.9 2540.23,1013.58 2545.53,1013.58 2550.84,1018.88 2550.84,1024.18 2548.16,1026.86 2548.16,1032.16 2552.5,1036.5 2558,1042 v1(2558,1118)
  Bottom Layer w6: J1.25@2510.37,1236.74 2510.37,1159.63 2552,1118 v1(2558,1118)
  other v1: 1960.02,659.98 557,1077
EM_D5: J1.26@2510.37,1329.26 U2.10 U3.14 U4.40 | length 6438.6
  Top Layer w6: U3.14@1454.74,256.62 1454.74,402.74 1468.99,416.99 1484,416.99 1489.1,416.99 1492.5,420.39 1492.5,427.6 1495.9,431 1506.1,431 1509.5,427.6 1509.5,416.99 1509.5,382.39 1512.9,378.99 1523.1,378.99 1526.5,382.39 1526.5,416.99 1526.5,427.6 1529.9,431 1540.1,431 1543.5,427.6 1543.5,416.99 1543.5,385.37 1546.9,381.97 1557.1,381.97 1560.5,385.37 1560.5,416.99 1560.5,427.6 1563.9,431 1574.1,431 1577.5,427.6 1577.5,416.99 1577.5,385.4 1580.9,382 1591.1,382 1594.5,385.4 1594.5,416.99 1594.5,427.6 1597.9,431 1608.1,431 1611.5,427.6 1611.5,416.99 1611.5,385.4 1614.9,382 1625.1,382 1628.5,385.4 1628.5,416.99 1628.5,446.12 1631.9,449.52 1642.1,449.52 1645.5,446.12 1645.5,416.99 1645.5,385.4 1648.9,382 1659.1,382 1662.5,385.4 1662.5,416.99 1662.5,451.59 1665.9,454.99 1676.1,454.99 1679.5,451.59 1679.5,416.99 1679.5,385.4 1682.9,382 1693.1,382 1696.5,385.4 1696.5,416.99 1696.5,451.59 1699.9,454.99 1710.1,454.99 1713.5,451.59 1713.5,416.99 1713.5,385.4 1716.9,382 1727.1,382 1730.5,385.4 1730.5,416.99 1730.5,451.59 1733.9,454.99 1744.1,454.99 1747.5,451.59 1747.5,416.99 1747.5,382.39 1750.9,378.99 1761.1,378.99 1764.5,382.39 1764.5,413.59 1767.9,416.99 1778,416.99 1814.99,416.99 1822.5,424.5 1826.11,428.11 1826.11,432.91 1782.01,477.01 1782.01,481.82 1789.22,489.03 1794.03,489.03 1840.53,442.53 1845.34,442.53 1852.55,449.74 1852.55,454.55 1806.05,501.06 1806.05,505.86 1813.26,513.08 1818.07,513.08 1862.17,468.98 1866.98,468.98 1880,482 1880,566 1910.98,596.98 v1(1959.02,596.98) v1@1962.02,596.98
  Top Layer w8: v1@518,1076 518.1,1075.9 U4.40@518.1,1033.8
  Top Layer w15: U3.14@1454.74,256.62 1454.74,222.26 v1@1455,222 ; v1@1962.02,596.98 U2.10@2003.64,596.98
  Signal Layer 3 w6: v1@518,1073 518,1065.5 518,1054.25 514.25,1050.5 507.93,1050.5 504.18,1046.75 504.18,1039.25 507.93,1035.5 518,1035.5 528.07,1035.5 531.82,1031.75 531.82,1024.25 528.07,1020.5 518,1020.5 507.93,1020.5 504.18,1016.75 504.18,1009.25 507.93,1005.5 518,1005.5 528.07,1005.5 531.82,1001.75 531.82,994.25 528.07,990.5 518,990.5 507.93,990.5 504.18,986.75 504.18,979.25 507.93,975.5 518,975.5 528.07,975.5 531.82,971.75 531.82,964.25 528.07,960.5 518,960.5 507.93,960.5 504.18,956.75 504.18,949.25 507.93,945.5 514.25,945.5 518,941.75 518,937 518,741 902,357 902,211 997,116 1354,116 v1@1455,217 ; v1@1962.02,596.98 1888,671 1888,1151 1916.5,1179.5 1928,1179.5 1933.1,1179.5 1936.5,1182.9 1936.5,1210.1 1939.9,1213.5 1950.1,1213.5 1953.5,1210.1 1953.5,1179.5 1953.5,1148.9 1956.9,1145.5 1967.1,1145.5 1970.5,1148.9 1970.5,1179.5 1970.5,1210.1 1973.9,1213.5 1984.1,1213.5 1987.5,1210.1 1987.5,1179.5 1987.5,1148.9 1990.9,1145.5 2001.1,1145.5 2004.5,1148.9 2004.5,1179.5 2004.5,1210.1 2007.9,1213.5 2018.1,1213.5 2021.5,1210.1 2021.5,1179.5 2021.5,1152.4 2024.9,1149 2035.1,1149 2038.5,1152.4 2038.5,1179.5 2038.5,1210.1 2041.9,1213.5 2052.1,1213.5 2055.5,1210.1 2055.5,1179.5 2055.5,1148.9 2058.9,1145.5 2069.1,1145.5 2072.5,1148.9 2072.5,1179.5 2072.5,1210.1 2075.9,1213.5 2086.1,1213.5 2089.5,1210.1 2089.5,1179.5 2089.5,1148.9 2092.9,1145.5 2103.1,1145.5 2106.5,1148.9 2106.5,1179.5 2106.5,1210.1 2109.9,1213.5 2120.1,1213.5 2123.5,1210.1 2123.5,1179.5 2123.5,1148.9 2126.9,1145.5 2137.1,1145.5 2140.5,1148.9 2140.5,1179.5 2140.5,1210.1 2143.9,1213.5 2154.1,1213.5 2157.5,1210.1 2157.5,1179.5 2157.5,1148.9 2160.9,1145.5 2171.1,1145.5 2174.5,1148.9 2174.5,1179.5 2174.5,1210.1 2177.9,1213.5 2188.1,1213.5 2191.5,1210.1 2191.5,1182.9 2194.9,1179.5 2207.5,1179.5 2208.5,1180.5 2252.5,1224.5 2261,1224.5 2266.1,1224.5 2269.5,1227.9 2269.5,1243.73 2272.9,1247.13 2283.1,1247.13 2286.5,1243.73 2286.5,1224.5 2286.5,1214.4 2289.9,1211 2300.1,1211 2303.5,1214.4 2303.5,1224.5 2303.5,1243.73 2306.9,1247.13 2317.1,1247.13 2320.5,1243.73 2320.5,1227.9 2323.9,1224.5 2375,1224.5 2379.5,1224.5 2524,1369 2524,1436 v1(2526,1438)
  Bottom Layer w6: J1.26@2510.37,1329.26 2510.37,1417.2 ; 2510.37,1417.69 2510.37,1417.2 ; v1@2524,1437 2524,1432.83 2525,1431.83 2510.37,1417.2
  other v1: 1455,214 518,1077
EM_D6: J1.27@2494.62,1236.74 U2.11 U3.15 U4.42 | length 6455.5
  Top Layer w6: v1@1486,297 1558,369 1732,369 1765,336 1765,176 1689,100 1508,100 1505,97 1505,82 1507,80 1726,80 1731.1,80 1734.5,83.4 1734.5,124.6 1737.9,128 1748.1,128 1751.5,124.6 1751.5,83.4 1754.9,80 1783,80 1807,80 1815,88 1815,90 1815,102.1 1811.6,105.5 1784.4,105.5 1781,108.9 1781,119.1 1784.4,122.5 1815,122.5 1845.6,122.5 1849,125.9 1849,136.1 1845.6,139.5 1815,139.5 1784.4,139.5 1781,142.9 1781,153.1 1784.4,156.5 1815,156.5 1845.6,156.5 1849,159.9 1849,170.1 1845.6,173.5 1815,173.5 1784.4,173.5 1781,176.9 1781,187.1 1784.4,190.5 1815,190.5 1845.6,190.5 1849,193.9 1849,204.1 1845.6,207.5 1815,207.5 1784.4,207.5 1781,210.9 1781,221.1 1784.4,224.5 1815,224.5 1845.6,224.5 1849,227.9 1849,238.1 1845.6,241.5 1815,241.5 1784.4,241.5 1781,244.9 1781,255.1 1784.4,258.5 1815,258.5 1845.6,258.5 1849,261.9 1849,272.1 1845.6,275.5 1815,275.5 1784.4,275.5 1781,278.9 1781,289.1 1784.4,292.5 1815,292.5 1845.6,292.5 1849,295.9 1849,306.1 1845.6,309.5 1815,309.5 1784.4,309.5 1781,312.9 1781,323.1 1784.4,326.5 1815,326.5 1845.6,326.5 1849,329.9 1849,340.1 1845.6,343.5 1818.4,343.5 1815,346.9 1815,352 1815,362 1817.65,364.65 1817.65,369.95 1797.5,390.11 1797.5,395.41 1802.8,400.71 1808.11,400.71 1830.91,377.91 1853.71,355.11 1859.02,355.11 1864.32,360.41 1864.32,365.71 1844.17,385.86 1844.17,391.17 1861.5,408.5 1908,455 1908,463.5 1908,477.1 1911.4,480.5 1916.6,480.5 1920,483.9 1920,494.1 1916.6,497.5 1908,497.5 1896.4,497.5 1893,500.9 1893,511.1 1896.4,514.5 1904.6,514.5 1908,517.9 1908,531.5 1908,532 1908,537.49 1936,565.49 U2.11@2003.64,565.49
  Top Layer w8: U4.42@478.73,1033.8 478.73,1075.73 v1@479,1076
  Top Layer w15: U3.15@1486.24,256.62 1486.24,290.24 v1@1487,291 ; U2.11@2003.64,565.49 v1@2045.49,565.49
  Signal Layer 3 w6: v1@479,1073 479,742 878.5,342.5 878.5,213.5 990,102 1387,102 1486,201 v1@1486,297
  Bottom Layer w6: v1@2045.49,565.49 2079.98,531 2132,531 2139.75,531 2143.5,534.75 2143.5,541.25 2147.25,545 2154.75,545 2158.5,541.25 2158.5,531 2158.5,520.75 2162.25,517 2169.75,517 2173.5,520.75 2173.5,531 2173.5,541.25 2177.25,545 2184.75,545 2188.5,541.25 2188.5,531 2188.5,520.75 2192.25,517 2199.75,517 2203.5,520.75 2203.5,531 2203.5,541.25 2207.25,545 2214.75,545 2218.5,541.25 2218.5,531 2218.5,520.75 2222.25,517 2229.75,517 2233.5,520.75 2233.5,531 2233.5,541.25 2237.25,545 2244.75,545 2248.5,541.25 2248.5,531 2248.5,520.75 2252.25,517 2259.75,517 2263.5,520.75 2263.5,531 2263.5,541.25 2267.25,545 2274.75,545 2278.5,541.25 2278.5,531 2278.5,520.75 2282.25,517 2289.75,517 2293.5,520.75 2293.5,531 2293.5,541.25 2297.25,545 2304.75,545 2308.5,541.25 2308.5,534.75 2312.25,531 2323.5,531 2349.5,557 2388,557 2391.75,557 2395.5,560.75 2395.5,571.25 2399.25,575 2406.75,575 2410.5,571.25 2410.5,557 2413.51,553.99 2422.49,553.99 2425.5,557 2425.5,571.25 2429.25,575 2436.75,575 2440.5,571.25 2440.5,557 2440.5,542.75 2444.25,539 2451.75,539 2455.5,542.75 2455.5,557 2455.5,571.25 2459.25,575 2466.75,575 2470.5,571.25 2470.5,560.75 2474.25,557 2485.5,557 2486,557 2500,543 2528,543 2610,625 2610,1034 2495.62,1148.38 J1.27@2495.62,1236.74
  other v1: 1486,300 2047.49,565.49 479,1077
EM_D7: J1.28@2494.62,1329.26 U2.13 U3.16 U4.44 | length 6419.5
  Top Layer w6: U3.16@1517.73,256.62 1517.73,295 1575.73,353 1721,353 1749,325 1749,184 1681,116 1490,116 1486,112 1486,67 1490,63 1868,63 1879,74 1879,101 1879,106.1 1875.6,109.5 1868.4,109.5 1865,112.9 1865,123.1 1868.4,126.5 1879,126.5 1889.6,126.5 1893,129.9 1893,140.1 1889.6,143.5 1879,143.5 1868.4,143.5 1865,146.9 1865,157.1 1868.4,160.5 1879,160.5 1889.6,160.5 1893,163.9 1893,174.1 1889.6,177.5 1879,177.5 1868.4,177.5 1865,180.9 1865,191.1 1868.4,194.5 1879,194.5 1889.6,194.5 1893,197.9 1893,208.1 1889.6,211.5 1879,211.5 1868.4,211.5 1865,214.9 1865,225.1 1868.4,228.5 1879,228.5 1888.71,228.5 1892.11,231.9 1892.11,242.1 1888.71,245.5 1879,245.5 1868.4,245.5 1865,248.9 1865,259.1 1868.4,262.5 1879,262.5 1889.6,262.5 1893,265.9 1893,276.1 1889.6,279.5 1879,279.5 1868.4,279.5 1865,282.9 1865,293.1 1868.4,296.5 1879,296.5 1888.25,296.5 1891.65,299.9 1891.65,310.1 1888.25,313.5 1879,313.5 1868.4,313.5 1865,316.9 1865,327.1 1868.4,330.5 1875.6,330.5 1879,333.9 1879,347.5 1879,353 1879,355 1890,366 1893.61,369.61 1893.61,374.41 1887.76,380.26 1887.76,385.07 1894.97,392.28 1899.78,392.28 1905.63,386.44 1910.44,386.44 1921.5,397.5 1933,409 1933,488.5 1947,502.5 U2.13@2003.64,502.5
  Top Layer w8: U4.44@439.36,1033.8 439.36,1075.36 v1@440,1076
  Top Layer w15: U3.16@1517.73,256.62 1517.73,222.27 v1@1518,222 ; U2.13@2003.64,502.5 2041.5,502.5 v1@2042,502
  Signal Layer 3 w6: v1@440,1073 440,889 440,883.9 443.4,880.5 445.83,880.5 449.23,877.1 449.23,866.9 445.83,863.5 443.4,863.5 440,860.1 440,851 440,736 852.5,323.5 852.5,215.5 980,88 1403,88 1518,203 v1(1518,214) v1@1518,217 ; v1@2042,502 2047,502 2084,539 2084,576 2065,595 2006,595 1978,567 1908,567 1863,612 1863,1023 1854,1032 1854,1218 1857.5,1221.5 1858.02,1222.02 1865.98,1229.98 1865.98,1235.28 1845.37,1255.9 1845.37,1261.2 1850.67,1266.5 1855.97,1266.5 1879.24,1243.24 1902.5,1219.97 1907.81,1219.97 1913.11,1225.28 1913.11,1230.58 1889.84,1253.84 1866.58,1277.11 1866.58,1282.41 1871.88,1287.72 1877.18,1287.72 1900.45,1264.45 1923.72,1241.18 1929.02,1241.18 1934.32,1246.49 1934.32,1251.79 1911.06,1275.06 1887.79,1298.32 1887.79,1303.63 1893.09,1308.93 1898.4,1308.93 1921.66,1285.66 1944.93,1262.4 1950.23,1262.4 1955.54,1267.7 1955.54,1273 1932.27,1296.27 1909,1319.54 1909,1324.84 1914.31,1330.14 1919.61,1330.14 1942.88,1306.88 1966.14,1283.61 1971.45,1283.61 1976.75,1288.91 1976.75,1294.22 1953.48,1317.48 1930.22,1340.75 1930.22,1346.05 1935.52,1351.36 1940.82,1351.36 1961.44,1330.74 1966.74,1330.74 1974.7,1338.7 1980,1344 1989,1344 2020,1313 2085,1313 2105,1333 2439,1333 2495,1389 v1(2495,1432)
  Bottom Layer w6: J1.28@2494.62,1329.26 2494.62,1431.62 v1(2495,1432)
  other v1: 2048,502 440,1077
